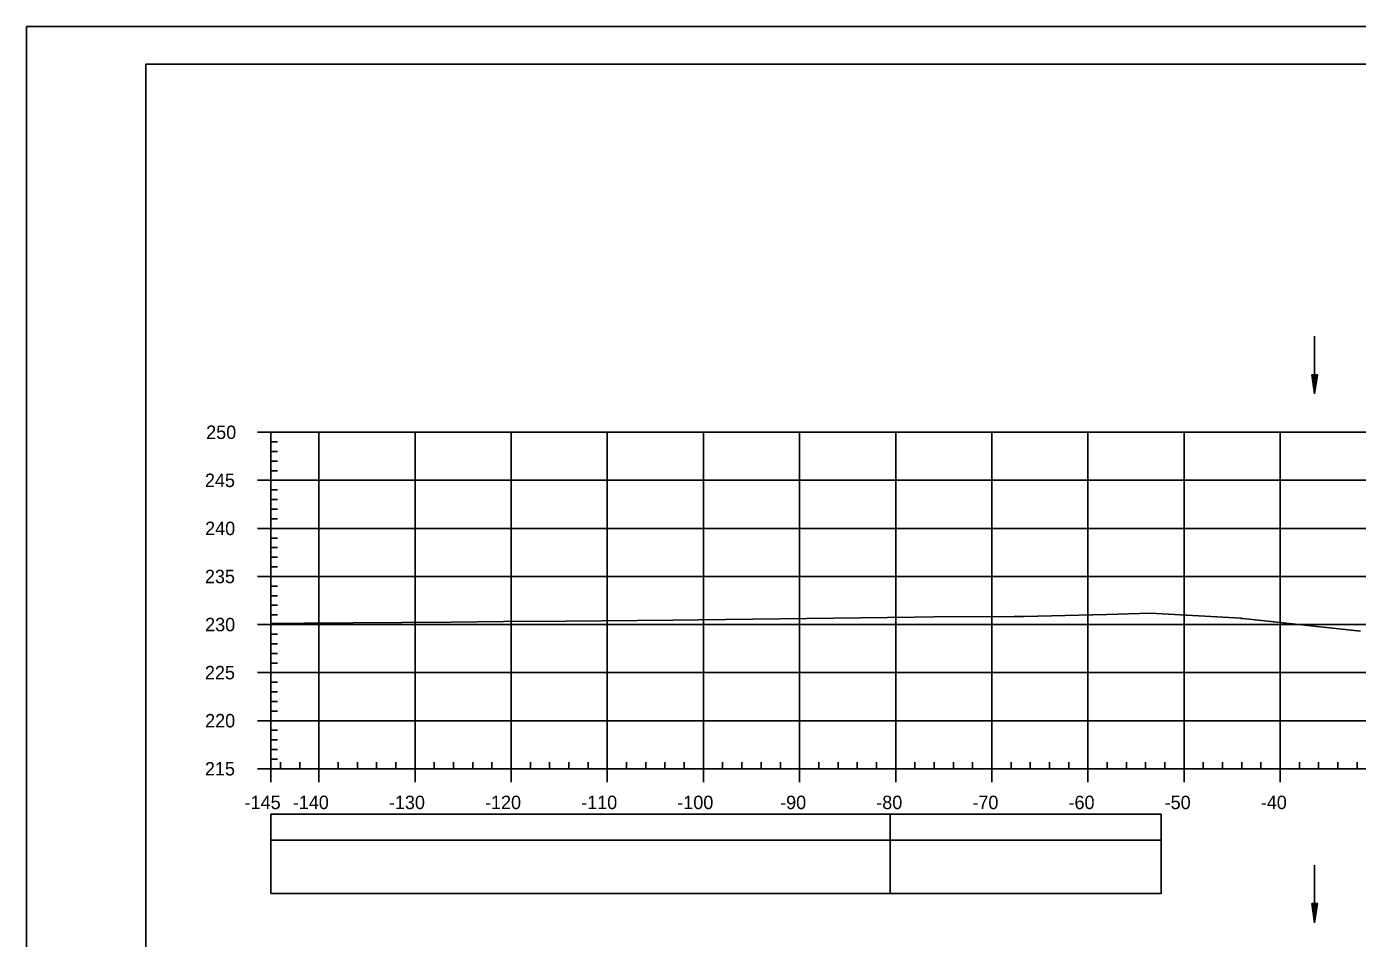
# Model space of a CAD drawing. Extents: x 1386544 to 1388153, y 379785 to 390999.
# Drawn here: x 1387195.6 to 1387334.1, y 383495.3 to 383590.1 of the extents above; entities that cross this region are included whole.
import ezdxf

# ---------------------------------------------------------------- set-up
doc = ezdxf.new("R2010")
doc.units = 0
for name, color, linetype in [('R_Axis', 7, 'Continuous'), ('R_Axis Annot', 7, 'Continuous'), ('R_Border', 7, 'Continuous'), ('R_Exist Surface', 7, 'Continuous'), ('R_Grid', 7, 'Continuous'), ('R_No Plot', 7, 'Continuous'), ('R_Striping', 7, 'Continuous'), ('R_Water', 7, 'Continuous')]:
    doc.layers.add(name, color=color, linetype=linetype)

msp = doc.modelspace()

# ---------------------------------------------------------------- linework, layer by layer
at = {"layer": 'R_Axis'}
for p, q in [((1387219.64, 383547.91), (1387221.04, 383547.91)), ((1387221.04, 383512.91), (1387221.04, 383547.91)), ((1387221.04, 383546.91), (1387221.74, 383546.91)), ((1387221.04, 383545.91), (1387221.74, 383545.91)), ((1387221.04, 383544.91), (1387221.74, 383544.91)), ((1387221.04, 383543.91), (1387221.74, 383543.91)), ((1387219.64, 383542.91), (1387221.04, 383542.91)), ((1387221.04, 383541.91), (1387221.74, 383541.91)), ((1387221.04, 383540.91), (1387221.74, 383540.91)), ((1387221.04, 383539.91), (1387221.74, 383539.91)), ((1387221.04, 383538.91), (1387221.74, 383538.91)), ((1387219.64, 383537.91), (1387221.04, 383537.91)), ((1387221.04, 383536.91), (1387221.74, 383536.91)), ((1387221.04, 383535.91), (1387221.74, 383535.91)), ((1387221.04, 383534.91), (1387221.74, 383534.91)), ((1387219.64, 383532.91), (1387221.04, 383532.91)), ((1387221.04, 383533.91), (1387221.74, 383533.91)), ((1387221.04, 383531.91), (1387221.74, 383531.91)), ((1387221.04, 383530.91), (1387221.74, 383530.91)), ((1387221.04, 383529.91), (1387221.74, 383529.91)), ((1387221.04, 383528.91), (1387221.74, 383528.91)), ((1387219.64, 383527.91), (1387221.04, 383527.91)), ((1387221.04, 383526.91), (1387221.74, 383526.91)), ((1387221.04, 383525.91), (1387221.74, 383525.91)), ((1387221.04, 383524.91), (1387221.74, 383524.91)), ((1387221.04, 383523.91), (1387221.74, 383523.91)), ((1387219.64, 383522.91), (1387221.04, 383522.91)), ((1387221.04, 383521.91), (1387221.74, 383521.91)), ((1387221.04, 383520.91), (1387221.74, 383520.91)), ((1387221.04, 383519.91), (1387221.74, 383519.91)), ((1387221.04, 383518.91), (1387221.74, 383518.91)), ((1387219.64, 383517.91), (1387221.04, 383517.91)), ((1387221.04, 383516.91), (1387221.74, 383516.91)), ((1387221.04, 383515.91), (1387221.74, 383515.91)), ((1387221.04, 383514.91), (1387221.74, 383514.91)), ((1387221.04, 383513.91), (1387221.74, 383513.91)), ((1387222.04, 383512.91), (1387222.04, 383513.61)), ((1387224.04, 383512.91), (1387224.04, 383513.61)), ((1387228.04, 383512.91), (1387228.04, 383513.61)), ((1387230.04, 383512.91), (1387230.04, 383513.61)), ((1387232.04, 383512.91), (1387232.04, 383513.61)), ((1387234.04, 383512.91), (1387234.04, 383513.61)), ((1387238.04, 383512.91), (1387238.04, 383513.61)), ((1387240.04, 383512.91), (1387240.04, 383513.61)), ((1387242.04, 383512.91), (1387242.04, 383513.61)), ((1387244.04, 383512.91), (1387244.04, 383513.61)), ((1387248.04, 383512.91), (1387248.04, 383513.61)), ((1387250.04, 383512.91), (1387250.04, 383513.61)), ((1387252.04, 383512.91), (1387252.04, 383513.61)), ((1387254.04, 383512.91), (1387254.04, 383513.61)), ((1387258.04, 383512.91), (1387258.04, 383513.61)), ((1387260.04, 383512.91), (1387260.04, 383513.61)), ((1387262.04, 383512.91), (1387262.04, 383513.61)), ((1387264.04, 383512.91), (1387264.04, 383513.61)), ((1387268.04, 383512.91), (1387268.04, 383513.61)), ((1387270.04, 383512.91), (1387270.04, 383513.61)), ((1387272.04, 383512.91), (1387272.04, 383513.61)), ((1387274.04, 383512.91), (1387274.04, 383513.61)), ((1387278.04, 383512.91), (1387278.04, 383513.61)), ((1387280.04, 383512.91), (1387280.04, 383513.61)), ((1387282.04, 383512.91), (1387282.04, 383513.61)), ((1387284.04, 383512.91), (1387284.04, 383513.61)), ((1387288.04, 383512.91), (1387288.04, 383513.61)), ((1387290.04, 383512.91), (1387290.04, 383513.61)), ((1387292.04, 383512.91), (1387292.04, 383513.61)), ((1387294.04, 383512.91), (1387294.04, 383513.61)), ((1387298.04, 383512.91), (1387298.04, 383513.61)), ((1387300.04, 383512.91), (1387300.04, 383513.61)), ((1387302.04, 383512.91), (1387302.04, 383513.61)), ((1387304.04, 383512.91), (1387304.04, 383513.61)), ((1387308.04, 383512.91), (1387308.04, 383513.61)), ((1387310.04, 383512.91), (1387310.04, 383513.61)), ((1387312.04, 383512.91), (1387312.04, 383513.61)), ((1387314.04, 383512.91), (1387314.04, 383513.61)), ((1387318.04, 383512.91), (1387318.04, 383513.61)), ((1387320.04, 383512.91), (1387320.04, 383513.61)), ((1387322.04, 383512.91), (1387322.04, 383513.61)), ((1387324.04, 383512.91), (1387324.04, 383513.61)), ((1387328.04, 383512.91), (1387328.04, 383513.61)), ((1387330.04, 383512.91), (1387330.04, 383513.61)), ((1387332.04, 383512.91), (1387332.04, 383513.61)), ((1387334.04, 383512.91), (1387334.04, 383513.61)), ((1387219.64, 383512.91), (1387221.04, 383512.91)), ((1387221.04, 383512.91), (1387511.04, 383512.91)), ((1387221.04, 383511.51), (1387221.04, 383512.91)), ((1387226.04, 383511.51), (1387226.04, 383512.91)), ((1387236.04, 383511.51), (1387236.04, 383512.91)), ((1387246.04, 383511.51), (1387246.04, 383512.91)), ((1387256.04, 383511.51), (1387256.04, 383512.91)), ((1387266.04, 383511.51), (1387266.04, 383512.91)), ((1387276.04, 383511.51), (1387276.04, 383512.91)), ((1387286.04, 383511.51), (1387286.04, 383512.91)), ((1387296.04, 383511.51), (1387296.04, 383512.91)), ((1387306.04, 383511.51), (1387306.04, 383512.91)), ((1387316.04, 383511.51), (1387316.04, 383512.91)), ((1387326.04, 383511.51), (1387326.04, 383512.91))]:
    msp.add_line(p, q, dxfattribs=at)
at = {"layer": 'R_Axis Annot'}
for points in [[(1387221.04, 383505.47), (1387285.47, 383505.47), (1387285.47, 383508.18), (1387221.04, 383508.18)], [(1387221.04, 383499.94), (1387285.47, 383499.94), (1387285.47, 383505.47), (1387221.04, 383505.47)]]:
    msp.add_lwpolyline(points, close=True, dxfattribs=at)
at = {"layer": 'R_Border'}
for p, q in [((1387208.04, 383586.21), (1387524.22, 383586.21)), ((1387208.04, 383380.75), (1387208.04, 383586.21))]:
    msp.add_line(p, q, dxfattribs=at)
at = {"layer": 'R_Exist Surface'}
msp.add_lwpolyline([(1387221.04, 383528.03), (1387224.53, 383528.07), (1387239.76, 383528.15), (1387245.25, 383528.22), (1387251.79, 383528.26), (1387262.88, 383528.36), (1387265.55, 383528.41), (1387288, 383528.68), (1387290.05, 383528.71), (1387298.35, 383528.73), (1387299.39, 383528.73), (1387299.4, 383528.73), (1387305.1, 383528.9), (1387307.99, 383528.96), (1387312.56, 383529.09), (1387321.95, 383528.56), (1387322.01, 383528.55), (1387322.15, 383528.54), (1387334.41, 383527.21)], dxfattribs=at)
at = {"layer": 'R_Grid'}
for p, q in [((1387221.04, 383547.91), (1387511.04, 383547.91)), ((1387226.04, 383512.91), (1387226.04, 383547.91)), ((1387226.04, 383512.91), (1387226.04, 383547.91)), ((1387236.04, 383512.91), (1387236.04, 383547.91)), ((1387236.04, 383512.91), (1387236.04, 383547.91)), ((1387246.04, 383512.91), (1387246.04, 383547.91)), ((1387246.04, 383512.91), (1387246.04, 383547.91)), ((1387256.04, 383512.91), (1387256.04, 383547.91)), ((1387256.04, 383512.91), (1387256.04, 383547.91)), ((1387266.04, 383512.91), (1387266.04, 383547.91)), ((1387266.04, 383512.91), (1387266.04, 383547.91)), ((1387276.04, 383512.91), (1387276.04, 383547.91)), ((1387276.04, 383512.91), (1387276.04, 383547.91)), ((1387286.04, 383512.91), (1387286.04, 383547.91)), ((1387286.04, 383512.91), (1387286.04, 383547.91)), ((1387296.04, 383512.91), (1387296.04, 383547.91)), ((1387296.04, 383512.91), (1387296.04, 383547.91)), ((1387306.04, 383512.91), (1387306.04, 383547.91)), ((1387306.04, 383512.91), (1387306.04, 383547.91)), ((1387316.04, 383512.91), (1387316.04, 383547.91)), ((1387316.04, 383512.91), (1387316.04, 383547.91)), ((1387326.04, 383512.91), (1387326.04, 383547.91)), ((1387326.04, 383512.91), (1387326.04, 383547.91)), ((1387221.04, 383542.91), (1387511.04, 383542.91)), ((1387221.04, 383512.91), (1387221.04, 383542.91)), ((1387221.04, 383542.91), (1387511.04, 383542.91)), ((1387221.04, 383512.91), (1387221.04, 383542.91)), ((1387221.04, 383537.91), (1387511.04, 383537.91)), ((1387221.04, 383537.91), (1387511.04, 383537.91)), ((1387221.04, 383532.91), (1387511.04, 383532.91)), ((1387221.04, 383532.91), (1387511.04, 383532.91)), ((1387221.04, 383527.91), (1387511.04, 383527.91)), ((1387221.04, 383527.91), (1387511.04, 383527.91)), ((1387221.04, 383522.91), (1387511.04, 383522.91)), ((1387221.04, 383522.91), (1387511.04, 383522.91)), ((1387221.04, 383517.91), (1387511.04, 383517.91)), ((1387221.04, 383517.91), (1387511.04, 383517.91)), ((1387221.04, 383512.91), (1387511.04, 383512.91)), ((1387221.04, 383512.91), (1387511.04, 383512.91))]:
    msp.add_line(p, q, dxfattribs=at)
at = {"layer": 'R_No Plot'}
msp.add_line((1387195.64, 383590.1), (1387528.97, 383590.1), dxfattribs=at)
for points in [[(1387195.63, 383590.1), (1387528.97, 383590.1), (1387528.97, 383376.76), (1387195.63, 383376.76)], [(1387441.96, 383586.21), (1387461.58, 383586.21), (1387461.58, 383576.33), (1387477.69, 383576.33), (1387500.89, 383576.33), (1387500.89, 383551.99), (1387524.22, 383551.99), (1387524.22, 383380.75), (1387208.04, 383380.75), (1387208.04, 383586.21)]]:
    msp.add_lwpolyline(points, close=True, dxfattribs=at)
at = {"layer": 'R_Striping'}
for points in [[(1387285.47, 383505.47), (1387313.66, 383505.47), (1387313.66, 383508.18), (1387285.47, 383508.18)], [(1387285.47, 383499.95), (1387313.66, 383499.95), (1387313.66, 383505.47), (1387285.47, 383505.47)]]:
    msp.add_lwpolyline(points, close=True, dxfattribs=at)
at = {"layer": 'R_Water'}
for p, q in [((1387329.62, 383557.9), (1387329.62, 383551.9)), ((1387329.32, 383553.9), (1387329.62, 383551.9)), ((1387329.92, 383553.9), (1387329.32, 383553.9)), ((1387329.32, 383553.9), (1387329.62, 383551.9)), ((1387329.92, 383553.9), (1387329.32, 383553.9)), ((1387329.37, 383553.9), (1387329.62, 383552.24)), ((1387329.37, 383553.9), (1387329.62, 383552.24)), ((1387329.42, 383553.9), (1387329.62, 383552.58)), ((1387329.42, 383553.9), (1387329.62, 383552.58)), ((1387329.47, 383553.9), (1387329.62, 383552.91)), ((1387329.47, 383553.9), (1387329.62, 383552.91)), ((1387329.52, 383553.9), (1387329.62, 383553.25)), ((1387329.52, 383553.9), (1387329.62, 383553.25)), ((1387329.57, 383553.9), (1387329.62, 383553.59)), ((1387329.57, 383553.9), (1387329.62, 383553.59)), ((1387329.92, 383553.9), (1387329.62, 383551.9)), ((1387329.72, 383553.9), (1387329.62, 383553.25)), ((1387329.82, 383553.9), (1387329.62, 383552.58)), ((1387329.87, 383553.9), (1387329.62, 383552.24)), ((1387329.77, 383553.9), (1387329.62, 383552.91)), ((1387329.67, 383553.9), (1387329.62, 383553.59)), ((1387329.92, 383553.9), (1387329.62, 383551.9)), ((1387329.72, 383553.9), (1387329.62, 383553.25)), ((1387329.82, 383553.9), (1387329.62, 383552.58)), ((1387329.87, 383553.9), (1387329.62, 383552.24)), ((1387329.77, 383553.9), (1387329.62, 383552.91)), ((1387329.67, 383553.9), (1387329.62, 383553.59)), ((1387329.62, 383502.9), (1387329.62, 383496.9)), ((1387329.32, 383498.9), (1387329.62, 383496.9)), ((1387329.92, 383498.9), (1387329.32, 383498.9)), ((1387329.32, 383498.9), (1387329.62, 383496.9)), ((1387329.92, 383498.9), (1387329.32, 383498.9)), ((1387329.37, 383498.9), (1387329.62, 383497.24)), ((1387329.37, 383498.9), (1387329.62, 383497.24)), ((1387329.42, 383498.9), (1387329.62, 383497.58)), ((1387329.42, 383498.9), (1387329.62, 383497.58)), ((1387329.47, 383498.9), (1387329.62, 383497.91)), ((1387329.47, 383498.9), (1387329.62, 383497.91)), ((1387329.52, 383498.9), (1387329.62, 383498.25)), ((1387329.52, 383498.9), (1387329.62, 383498.25)), ((1387329.57, 383498.9), (1387329.62, 383498.59)), ((1387329.57, 383498.9), (1387329.62, 383498.59)), ((1387329.92, 383498.9), (1387329.62, 383496.9)), ((1387329.72, 383498.9), (1387329.62, 383498.25)), ((1387329.82, 383498.9), (1387329.62, 383497.58)), ((1387329.87, 383498.9), (1387329.62, 383497.24)), ((1387329.77, 383498.9), (1387329.62, 383497.91)), ((1387329.67, 383498.9), (1387329.62, 383498.59)), ((1387329.92, 383498.9), (1387329.62, 383496.9)), ((1387329.72, 383498.9), (1387329.62, 383498.25)), ((1387329.82, 383498.9), (1387329.62, 383497.58)), ((1387329.87, 383498.9), (1387329.62, 383497.24)), ((1387329.77, 383498.9), (1387329.62, 383497.91)), ((1387329.67, 383498.9), (1387329.62, 383498.59))]:
    msp.add_line(p, q, dxfattribs=at)

# ---------------------------------------------------------------- texts
at = {"layer": 'R_Axis Annot'}
for s, p in [('250', (1387214.31, 383547.21)), ('245', (1387214.18, 383542.21)), ('240', (1387214.2, 383537.21)), ('235', (1387214.18, 383532.21)), ('230', (1387214.2, 383527.21)), ('225', (1387214.18, 383522.21)), ('220', (1387214.2, 383517.21)), ('215', (1387214.18, 383512.21)), ('-145', (1387218.31, 383508.71)), ('-140', (1387223.32, 383508.71)), ('-130', (1387233.32, 383508.71)), ('-120', (1387243.32, 383508.71)), ('-110', (1387253.32, 383508.71)), ('-100', (1387263.32, 383508.71)), ('-90', (1387274.02, 383508.71)), ('-80', (1387284.02, 383508.71)), ('-70', (1387294.02, 383508.71)), ('-60', (1387304.02, 383508.71)), ('-50', (1387314.02, 383508.71)), ('-40', (1387324.02, 383508.71))]:
    msp.add_text(s, height=1.4, dxfattribs=at).set_placement(p)

doc.saveas('drawing.dxf')
